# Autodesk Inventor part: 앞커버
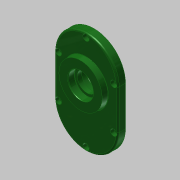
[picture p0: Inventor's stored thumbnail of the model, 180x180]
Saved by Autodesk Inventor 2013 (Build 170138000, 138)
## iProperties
Created: 2016-12
Part Number: 앞커버
Material: 알루미늄 6061
Document SubType Name: Modeling
Designer: mduedu
Density: 2.71 g/cm^3
Author: mduedu
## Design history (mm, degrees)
sketch "스케치1"
  geometry: L1 (40, -25)-(40, 25); L2 (-40, 25)-(-40, -25); L3 (-40, -25)-(40, 25); L4 (40, -25)-(-40, 25); A1 r 40 centre (0, 25) between (40, 25) and (-40, 25); A2 r 40 centre (0, -25) between (-40, -25) and (40, -25); 1 further point
  constraints: 8 end point, 4 point on circle, 4 tangent, 2 centre point, 2 midpoint, 1 parallel, 1 vertical
  dimensions: "d0" = 130 dimension on A2 A1; "d2" = 80 distance between parallel lines of L1 L2
extrude "돌출1" new body sketch "스케치1" distance "d3" = 10; taper "d4" = 0 deg
sketch "스케치2"
  geometry: C1 r 21 at (0, 11); 1 further point
  constraints: 1 centre point, 1 vertical alignment
  dimensions: "d5" = 42 diameter of C1; "d7" = 11 distance of C1.centre point (0, 0)
extrude "돌출2" join sketch "스케치2" distance "d8" = 7; taper "d9" = 0 deg
sketch "스케치3"
  geometry: C1 r 15 at (0, -33.1); C2 r 21 at (0, 11) reference; 1 further point
  constraints: 1 centre point, 1 vertical alignment
  dimensions: "d10" = 30 diameter of C1; "d71" = 44.1 distance of C1.centre C2.centre
extrude "돌출3" join sketch "스케치3" distance "d12" = 7; taper "d13" = 0 deg
sketch "스케치4"
  geometry: C1 r 28 at (0, 11); A1 r 21 centre (0, 11) between (8.978, -7.984) and (-8.978, -7.984) reference; 1 further point
  constraints: 1 centre point, 1 coincident
  dimensions: "d14" = 56 diameter of C1
extrude "돌출4" join sketch "스케치4" distance "d15" = 7; taper "d16" = -5 deg
hole "구멍1" diameter "d19" = 35; stored, may be unused: countersink angle "d23" = 90 deg, drill point angle "d25" = 0 deg; dims "d17" = 10, "d18" = 10, "d20" = 6, "d21" = 4, "d22" = 2, "d24" = 10
hole "구멍2" diameter "d28" = 22; stored, may be unused: countersink angle "d32" = 90 deg, drill point angle "d34" = 0 deg; dims "d26" = 10, "d27" = 10, "d29" = 6, "d30" = 4, "d31" = 2, "d33" = 7
hole "구멍3" diameter "d37" = 19; stored, may be unused: countersink angle "d41" = 90 deg, drill point angle "d43" = 0 deg; dims "d35" = 10, "d36" = 10, "d38" = 6, "d39" = 4, "d40" = 2, "d42" = 1
hole "구멍4" diameter "d46" = 32; stored, may be unused: countersink angle "d50" = 90 deg, drill point angle "d52" = 0 deg; dims "d47" = 6, "d48" = 4, "d49" = 2, "d51" = 8.3, "d89" = 10, "d90" = 10
hole "구멍5" diameter "d55" = 25; stored, may be unused: countersink angle "d59" = 90 deg, drill point angle "d61" = 0 deg; dims "d53" = 10, "d54" = 10, "d56" = 6, "d57" = 4, "d58" = 2, "d60" = 8
fillet "모깎기1" dims "d62" = 0.3
fillet "모깎기2" dims "d63" = 2
chamfer "모따기1" distance "d64" = 1; stored, may be unused: second distance "d65" = 2, angle "d66" = 45 deg
chamfer "모따기2" distance "d91" = 0.8; stored, may be unused: second distance "d92" = 2, angle "d93" = 30 deg
fillet "모깎기4" dims "d68" = 2
fillet "모깎기5" dims "d69" = 0.3
fillet "모깎기6" dims "d70" = 2
sketch "스케치5"
  geometry: L1 (-40, 25)-(-40, -25) reference; L2 (40, -25)-(40, 25) reference; L3 (35, 25)-(35, -25); L4 (-35, -25)-(-35, 25); A1 r 40 centre (0, 25) between (40, 25) and (-40, 25) reference; A2 r 40 centre (0, -25) between (-40, -25) and (40, -25) reference; A3 r 35 centre (0, 25) between (35, 25) and (-35, 25); A4 r 35 centre (0, -25) between (-35, -25) and (35, -25); 2 further points
  constraints: 5 point on circle, 4 end point, 2 centre point, 1 vertical alignment, 3 other
  dimensions: "d72" = 5 distance between parallel lines of L2 L3
sketch "스케치7"
  geometry: 1 further point
  constraints: 1 other
hole "구멍7" sketch "스케치7" at (0, 60) diameter "d80" = 4.5; stored, may be unused: countersink angle "d84" = 90 deg, drill point angle "d86" = 0 deg; dims "d81" = 6, "d82" = 8, "d83" = 4.6, "d85" = 8
node "솔리드1"
pattern_linear "직사각형 패턴1"
